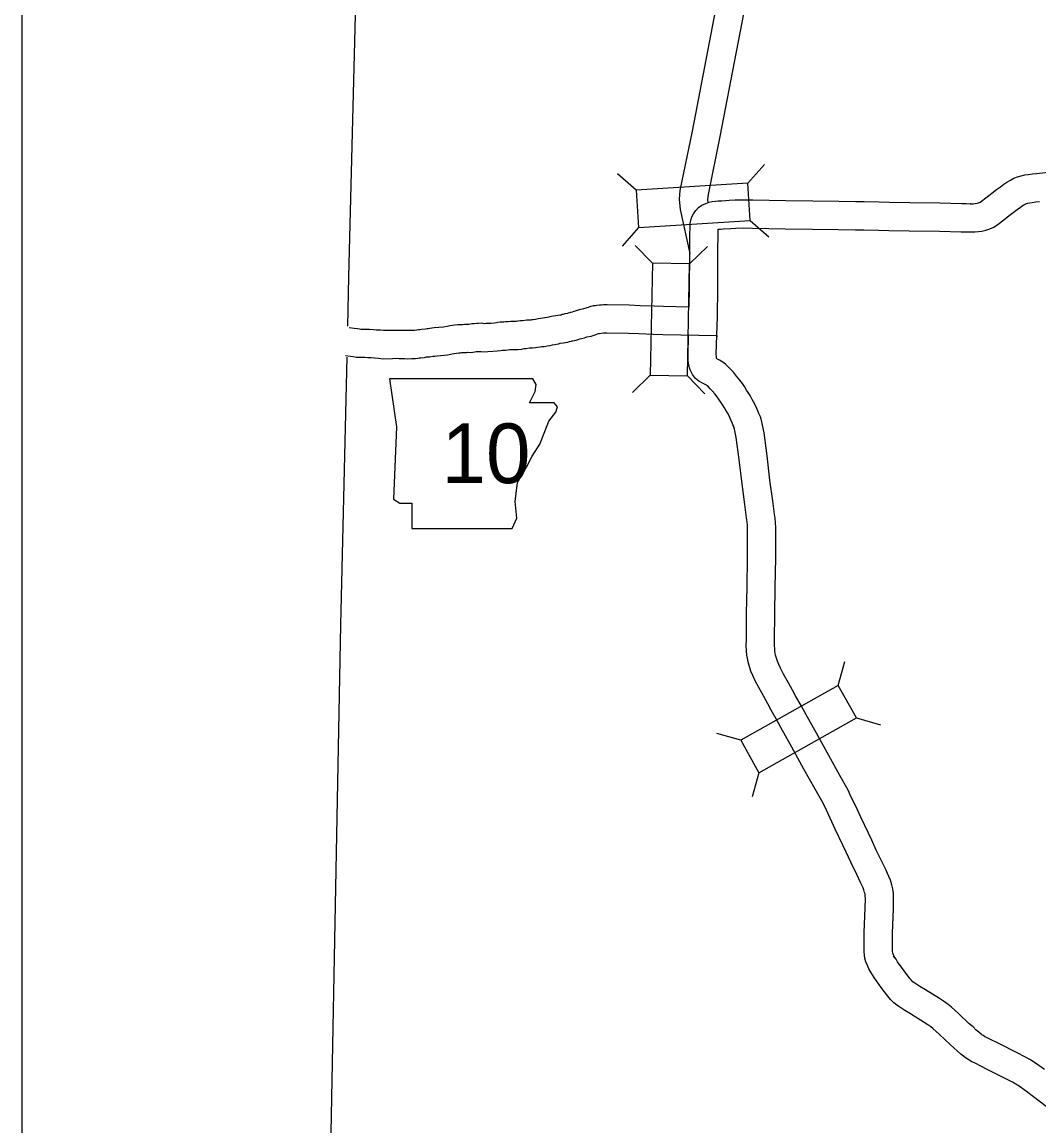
# Model space of a CAD drawing. Extents: x 1370567 to 1373900, y 377514 to 379648.
# Drawn here: x 1370727.3 to 1370835.2, y 379043.8 to 379160.9 of the extents above; entities that cross this region are included whole.
import ezdxf

# ---------------------------------------------------------------- set-up
doc = ezdxf.new("R2010")
doc.units = 0
doc.layers.add('Default', color=7, linetype='Continuous')
doc.layers.add('Survey Symbols', color=7, linetype='Continuous')

msp = doc.modelspace()

# ---------------------------------------------------------------- linework, layer by layer
at = {"layer": 'Default'}
for p, q in [((1370804.33, 379143.81), (1370806.08, 379145.79)), ((1370792.48, 379143.06), (1370790.5, 379144.81)), ((1370827.99, 379141.63), (1370827.95, 379141.63)), ((1370792.72, 379139.11), (1370790.98, 379137.13)), ((1370804.58, 379139.86), (1370806.56, 379138.11)), ((1370827.95, 379138.63), (1370827.99, 379138.63)), ((1370794.19, 379135.31), (1370792.36, 379137.21)), ((1370798.15, 379135.24), (1370800.05, 379137.07)), ((1370788.48, 379127.85), (1370788.56, 379127.87)), ((1370793.97, 379123.43), (1370792.07, 379121.6)), ((1370797.93, 379123.36), (1370799.77, 379121.46)), ((1370813.93, 379090.5), (1370814.64, 379093.04)), ((1370815.87, 379087.05), (1370818.41, 379086.33)), ((1370803.57, 379084.68), (1370801.03, 379085.39)), ((1370805.51, 379081.23), (1370804.8, 379078.68)), ((1370815.8, 379077.68), (1370815.28, 379078.73)), ((1370813.08, 379076.4), (1370812.67, 379077.25)), ((1370819.93, 379061.58), (1370819.79, 379061.82)), ((1370817.22, 379060.29), (1370817.37, 379060.04))]:
    msp.add_line(p, q, dxfattribs=at)
for points in [[(1370761.86, 379128.63), (1370761.98, 379133.85), (1370762.81, 379167.24), (1370763.57, 379194.87), (1370764.84, 379244.73)], [(1370802.56, 379171.53), (1370802.51, 379171.1), (1370802.02, 379168.37), (1370801.85, 379167.28), (1370798.42, 379149.33), (1370797.12, 379143.03), (1370797.05, 379142.1), (1370797.13, 379141), (1370798.16, 379136.33)], [(1370805.54, 379171.16), (1370805.47, 379170.65), (1370804.98, 379167.88), (1370804.81, 379166.77), (1370801.36, 379148.75), (1370800.1, 379142.6), (1370800.06, 379142.09), (1370800.09, 379141.73)], [(1370827.95, 379141.63), (1370828.25, 379141.63), (1370828.47, 379141.65), (1370828.68, 379141.68), (1370828.82, 379141.71), (1370828.9, 379141.74), (1370828.99, 379141.78), (1370829.15, 379141.89), (1370829.6, 379142.24), (1370830.22, 379142.75), (1370830.72, 379143.12), (1370831.14, 379143.43), (1370831.52, 379143.71), (1370831.83, 379143.93), (1370832.2, 379144.14), (1370832.58, 379144.33), (1370832.96, 379144.49), (1370833.35, 379144.6), (1370833.73, 379144.68), (1370834.1, 379144.74), (1370834.56, 379144.79), (1370834.99, 379144.84), (1370836.84, 379145.03)], [(1370798.11, 379130.7), (1370798.14, 379132.71), (1370798.16, 379136.34), (1370798.16, 379136.77), (1370798.17, 379138.26), (1370798.19, 379139.24), (1370798.21, 379139.54), (1370798.3, 379140.01), (1370798.43, 379140.32), (1370798.56, 379140.57), (1370798.8, 379140.92), (1370799.1, 379141.22), (1370799.46, 379141.47), (1370799.86, 379141.66), (1370800.23, 379141.78), (1370800.55, 379141.86), (1370800.89, 379141.9), (1370801.19, 379141.93), (1370801.58, 379141.95), (1370802.35, 379142), (1370802.95, 379142.03), (1370803.83, 379142.05), (1370804.85, 379142.04), (1370808.35, 379141.97), (1370811.24, 379141.94), (1370813.98, 379141.89), (1370815.8, 379141.85), (1370816.67, 379141.85), (1370818.28, 379141.81), (1370819.36, 379141.8), (1370821.52, 379141.75), (1370824.72, 379141.71), (1370827.04, 379141.65), (1370827.52, 379141.64), (1370827.99, 379141.63)], [(1370827.99, 379138.63), (1370828.41, 379138.64), (1370828.81, 379138.67), (1370829.18, 379138.73), (1370829.59, 379138.81), (1370830.02, 379138.95), (1370830.45, 379139.15), (1370830.9, 379139.44), (1370831.49, 379139.91), (1370832.06, 379140.38), (1370832.49, 379140.7), (1370832.92, 379141.01), (1370833.27, 379141.27), (1370833.45, 379141.4), (1370833.63, 379141.5), (1370833.83, 379141.6), (1370833.95, 379141.65), (1370834.07, 379141.68), (1370834.28, 379141.73), (1370834.52, 379141.77), (1370834.9, 379141.81), (1370835.3, 379141.85)], [(1370801.04, 379127.65), (1370801.09, 379129.67), (1370801.14, 379132.68), (1370801.16, 379136.33), (1370801.16, 379136.77), (1370801.17, 379138.22), (1370801.18, 379138.91), (1370801.23, 379138.92), (1370801.43, 379138.94), (1370801.75, 379138.96), (1370802.51, 379139), (1370803.06, 379139.03), (1370803.86, 379139.05), (1370804.82, 379139.04), (1370808.3, 379138.97), (1370811.2, 379138.94), (1370813.93, 379138.89), (1370815.77, 379138.85), (1370816.63, 379138.85), (1370818.23, 379138.81), (1370819.31, 379138.8), (1370821.46, 379138.75), (1370824.66, 379138.71), (1370826.96, 379138.65), (1370827.47, 379138.64), (1370827.95, 379138.63)], [(1370787.75, 379130.76), (1370787.94, 379130.81), (1370788.15, 379130.84), (1370788.3, 379130.87), (1370788.57, 379130.9), (1370788.71, 379130.89), (1370788.78, 379130.9), (1370788.99, 379130.93), (1370789.15, 379130.93), (1370789.2, 379130.93), (1370789.23, 379130.94), (1370789.28, 379130.94), (1370789.38, 379130.94), (1370791.74, 379130.88), (1370792.88, 379130.83), (1370794.37, 379130.78), (1370795.38, 379130.75), (1370798.11, 379130.7)], [(1370762, 379128.5), (1370762.55, 379128.42), (1370762.88, 379128.37), (1370763.1, 379128.34), (1370763.24, 379128.33), (1370763.74, 379128.33), (1370764.17, 379128.3), (1370764.57, 379128.28), (1370764.86, 379128.25), (1370765.34, 379128.24), (1370765.66, 379128.2), (1370765.77, 379128.19), (1370766.53, 379128.2), (1370767.05, 379128.22), (1370767.38, 379128.2), (1370767.65, 379128.21), (1370768.04, 379128.2), (1370768.2, 379128.19), (1370768.55, 379128.22), (1370768.76, 379128.21), (1370768.84, 379128.21), (1370768.94, 379128.22), (1370769.18, 379128.25), (1370769.37, 379128.26), (1370769.49, 379128.27), (1370769.69, 379128.33), (1370770.1, 379128.36), (1370770.26, 379128.37), (1370770.38, 379128.39), (1370770.58, 379128.43), (1370770.79, 379128.45), (1370771.03, 379128.48), (1370772.02, 379128.57), (1370772.41, 379128.64), (1370772.7, 379128.69), (1370772.96, 379128.72), (1370773.22, 379128.77), (1370773.55, 379128.8), (1370773.84, 379128.82), (1370774.04, 379128.82), (1370774.26, 379128.84), (1370774.59, 379128.86), (1370774.71, 379128.85), (1370775.01, 379128.91), (1370775.29, 379128.92), (1370775.55, 379128.94), (1370775.68, 379128.94), (1370776.01, 379128.99), (1370776.38, 379128.93), (1370776.53, 379128.95), (1370777.04, 379128.96), (1370777.38, 379129), (1370777.65, 379129.03), (1370777.79, 379129.06), (1370778.04, 379129.1), (1370778.32, 379129.1), (1370778.43, 379129.1), (1370778.61, 379129.12), (1370778.9, 379129.14), (1370779.17, 379129.15), (1370779.48, 379129.16), (1370779.78, 379129.17), (1370779.9, 379129.18), (1370780.2, 379129.23), (1370780.42, 379129.25), (1370780.88, 379129.32), (1370781.31, 379129.32), (1370781.42, 379129.34), (1370781.53, 379129.35), (1370781.79, 379129.39), (1370782.05, 379129.44), (1370782.33, 379129.47), (1370782.58, 379129.5), (1370782.79, 379129.54), (1370783.06, 379129.59), (1370783.25, 379129.62), (1370783.34, 379129.64), (1370783.5, 379129.68), (1370783.7, 379129.73), (1370783.96, 379129.78), (1370784.36, 379129.83), (1370784.46, 379129.84), (1370784.51, 379129.85), (1370784.62, 379129.89), (1370784.77, 379129.92), (1370784.94, 379129.98), (1370785.19, 379130.02), (1370785.21, 379130.02), (1370785.3, 379130.05), (1370785.52, 379130.11), (1370785.72, 379130.17), (1370785.88, 379130.21), (1370786.03, 379130.25), (1370786.14, 379130.29), (1370786.46, 379130.4), (1370786.93, 379130.49), (1370787.16, 379130.57), (1370787.28, 379130.61), (1370787.4, 379130.65), (1370787.65, 379130.74), (1370787.85, 379130.78)], [(1370761.6, 379125.53), (1370762.13, 379125.45), (1370762.41, 379125.41), (1370762.76, 379125.35), (1370763.16, 379125.33), (1370763.65, 379125.33), (1370763.97, 379125.31), (1370764.35, 379125.29), (1370764.69, 379125.26), (1370765.1, 379125.24), (1370765.35, 379125.21), (1370765.68, 379125.18), (1370766.62, 379125.21), (1370767.02, 379125.22), (1370767.32, 379125.2), (1370767.64, 379125.21), (1370767.9, 379125.2), (1370768.24, 379125.18), (1370768.61, 379125.21), (1370768.68, 379125.21), (1370769.04, 379125.21), (1370769.29, 379125.24), (1370769.45, 379125.26), (1370769.61, 379125.27), (1370770, 379125.31), (1370770.2, 379125.36), (1370770.32, 379125.37), (1370770.57, 379125.39), (1370770.9, 379125.43), (1370771.01, 379125.46), (1370771.1, 379125.46), (1370771.36, 379125.5), (1370772.43, 379125.59), (1370772.94, 379125.69), (1370773.15, 379125.72), (1370773.41, 379125.76), (1370773.63, 379125.8), (1370773.78, 379125.81), (1370773.94, 379125.82), (1370774.2, 379125.82), (1370774.48, 379125.85), (1370774.61, 379125.86), (1370774.91, 379125.85), (1370775.36, 379125.92), (1370775.47, 379125.93), (1370775.65, 379125.94), (1370775.95, 379125.94), (1370776.01, 379125.95), (1370776.29, 379125.9), (1370776.74, 379125.95), (1370777.25, 379125.97), (1370777.71, 379126.02), (1370778.06, 379126.06), (1370778.29, 379126.1), (1370778.3, 379126.1), (1370778.36, 379126.1), (1370778.61, 379126.1), (1370778.85, 379126.13), (1370779.06, 379126.14), (1370779.31, 379126.15), (1370779.57, 379126.16), (1370779.93, 379126.17), (1370780.32, 379126.2), (1370780.57, 379126.25), (1370780.75, 379126.26), (1370781.13, 379126.32), (1370781.48, 379126.33), (1370781.8, 379126.36), (1370781.98, 379126.39), (1370782.29, 379126.43), (1370782.47, 379126.47), (1370782.69, 379126.49), (1370783.04, 379126.54), (1370783.34, 379126.59), (1370783.59, 379126.64), (1370783.82, 379126.68), (1370784.01, 379126.72), (1370784.21, 379126.76), (1370784.34, 379126.8), (1370784.42, 379126.81), (1370784.76, 379126.85), (1370784.96, 379126.88), (1370785.23, 379126.94), (1370785.4, 379126.99), (1370785.61, 379127.04), (1370785.67, 379127.06), (1370785.7, 379127.06), (1370785.9, 379127.1), (1370786.11, 379127.16), (1370786.33, 379127.22), (1370786.5, 379127.27), (1370786.66, 379127.31), (1370786.97, 379127.4), (1370787.18, 379127.48), (1370787.22, 379127.49), (1370787.7, 379127.58), (1370788.11, 379127.72), (1370788.19, 379127.75), (1370788.38, 379127.81), (1370788.48, 379127.85)], [(1370788.56, 379127.87), (1370789, 379127.91), (1370789.14, 379127.92), (1370789.23, 379127.93), (1370789.24, 379127.94), (1370789.27, 379127.94), (1370789.32, 379127.94), (1370789.36, 379127.94), (1370791.65, 379127.88), (1370792.77, 379127.84), (1370794.27, 379127.78), (1370795.32, 379127.75), (1370801.04, 379127.65)], [(1370812.67, 379077.25), (1370812.31, 379077.99), (1370811.48, 379079.49), (1370810.29, 379081.62), (1370808.99, 379083.96), (1370807.84, 379086.02), (1370807.35, 379086.94), (1370806.82, 379087.86), (1370806.44, 379088.55), (1370806.01, 379089.32), (1370805.49, 379090.29), (1370805.11, 379091), (1370804.85, 379091.54), (1370804.66, 379092.03), (1370804.46, 379092.62), (1370804.36, 379093), (1370804.28, 379093.38), (1370804.22, 379093.73), (1370804.18, 379094.17), (1370804.16, 379094.74), (1370804.17, 379095.34), (1370804.19, 379098.18), (1370804.24, 379100.92), (1370804.29, 379104.06), (1370804.3, 379107.19), (1370804.29, 379107.51), (1370804.25, 379107.88), (1370804.2, 379108.28), (1370804, 379109.69), (1370803.71, 379111.9), (1370803.39, 379114.49), (1370803.08, 379116.83), (1370802.95, 379117.52), (1370802.9, 379117.75), (1370802.85, 379117.92), (1370802.83, 379118), (1370802.75, 379118.17), (1370802.65, 379118.42), (1370802.53, 379118.67), (1370802.38, 379119.03), (1370802.17, 379119.42), (1370802, 379119.73), (1370801.84, 379119.97), (1370801.67, 379120.23), (1370801.46, 379120.56), (1370801.28, 379120.82), (1370801.07, 379121.12), (1370800.82, 379121.44), (1370800.54, 379121.77), (1370800.34, 379121.99), (1370800.14, 379122.19), (1370800.02, 379122.31), (1370799.93, 379122.38), (1370799.86, 379122.42), (1370799.74, 379122.48), (1370799.5, 379122.59), (1370799.14, 379122.79), (1370798.76, 379123.09), (1370798.46, 379123.51), (1370798.24, 379123.92), (1370798.14, 379124.22), (1370798.05, 379124.53), (1370798, 379124.94), (1370797.99, 379125.28), (1370797.98, 379125.69), (1370798.04, 379127.58), (1370798.04, 379127.68)], [(1370815.28, 379078.73), (1370814.97, 379079.37), (1370814.1, 379080.95), (1370812.91, 379083.08), (1370811.61, 379085.42), (1370810.47, 379087.46), (1370809.98, 379088.38), (1370809.44, 379089.34), (1370809.06, 379090.01), (1370808.64, 379090.76), (1370808.13, 379091.71), (1370807.79, 379092.34), (1370807.61, 379092.72), (1370807.48, 379093.06), (1370807.33, 379093.5), (1370807.28, 379093.7), (1370807.23, 379093.94), (1370807.2, 379094.13), (1370807.18, 379094.36), (1370807.16, 379094.78), (1370807.17, 379095.31), (1370807.19, 379098.14), (1370807.24, 379100.87), (1370807.29, 379104.03), (1370807.31, 379107.25), (1370807.28, 379107.76), (1370807.22, 379108.25), (1370807.17, 379108.67), (1370806.97, 379110.09), (1370806.68, 379112.28), (1370806.37, 379114.87), (1370806.05, 379117.31), (1370805.89, 379118.13), (1370805.81, 379118.49), (1370805.73, 379118.75), (1370805.66, 379119.01), (1370805.51, 379119.36), (1370805.39, 379119.63), (1370805.27, 379119.9), (1370805.08, 379120.34), (1370804.8, 379120.86), (1370804.57, 379121.27), (1370804.36, 379121.6), (1370804.2, 379121.85), (1370803.96, 379122.22), (1370803.75, 379122.53), (1370803.48, 379122.9), (1370803.14, 379123.34), (1370802.79, 379123.74), (1370802.54, 379124.03), (1370802.22, 379124.36), (1370801.97, 379124.59), (1370801.67, 379124.82), (1370801.32, 379125.04), (1370801.05, 379125.18), (1370800.99, 379125.21), (1370800.99, 379125.33), (1370800.98, 379125.68), (1370801.04, 379127.65), (1370801.04, 379127.49)], [(1370759.6, 379016.99), (1370761.13, 379096.92), (1370761.78, 379125.33)], [(1370835.82, 379049.75), (1370834.97, 379050.34), (1370834.69, 379050.53), (1370834.45, 379050.68), (1370834.25, 379050.8), (1370833.82, 379051.03), (1370832.85, 379051.53), (1370831.11, 379052.42), (1370829.82, 379053.08), (1370829.46, 379053.25), (1370829.31, 379053.34), (1370829.18, 379053.42), (1370829.12, 379053.47), (1370828.85, 379053.69), (1370828.58, 379053.92), (1370828.24, 379054.25), (1370827.84, 379054.6), (1370826.68, 379055.68), (1370825.95, 379056.35), (1370825.59, 379056.65), (1370825.1, 379056.98), (1370824.66, 379057.27), (1370823.18, 379058.18), (1370822.6, 379058.54), (1370822.06, 379058.89), (1370821.89, 379059.02), (1370821.84, 379059.06), (1370821.66, 379059.24), (1370821.51, 379059.41), (1370820.91, 379060.21), (1370820.23, 379061.17), (1370820.06, 379061.44), (1370819.93, 379061.64), (1370819.85, 379061.78), (1370819.79, 379061.91), (1370819.72, 379062.08), (1370819.71, 379062.12), (1370819.7, 379062.25), (1370819.68, 379062.43), (1370819.67, 379062.74), (1370819.69, 379064.22), (1370819.78, 379066.8), (1370819.81, 379067.87), (1370819.78, 379068.42), (1370819.73, 379068.91), (1370819.62, 379069.33), (1370819.48, 379069.84), (1370819.31, 379070.23), (1370819.17, 379070.55), (1370819, 379070.91), (1370818.59, 379071.73), (1370817.97, 379073.03), (1370817.48, 379074.07), (1370817.13, 379074.82), (1370816.33, 379076.53), (1370815.8, 379077.68)], [(1370832.79, 379048.18), (1370832.42, 379048.38), (1370831.49, 379048.85), (1370829.74, 379049.75), (1370828.47, 379050.4), (1370828.05, 379050.6), (1370827.78, 379050.76), (1370827.45, 379050.96), (1370827.22, 379051.15), (1370826.93, 379051.38), (1370826.57, 379051.69), (1370826.2, 379052.04), (1370825.83, 379052.37), (1370824.65, 379053.48), (1370823.98, 379054.08), (1370823.77, 379054.25), (1370823.43, 379054.49), (1370823.05, 379054.74), (1370821.61, 379055.63), (1370821, 379056), (1370820.35, 379056.42), (1370820.01, 379056.67), (1370819.8, 379056.86), (1370819.47, 379057.18), (1370819.18, 379057.51), (1370818.48, 379058.44), (1370817.74, 379059.5), (1370817.55, 379059.8), (1370817.37, 379060.07), (1370817.16, 379060.43), (1370817.02, 379060.76), (1370816.86, 379061.17), (1370816.76, 379061.57), (1370816.72, 379061.88), (1370816.68, 379062.21), (1370816.67, 379062.72), (1370816.69, 379064.29), (1370816.78, 379066.91), (1370816.81, 379067.84), (1370816.79, 379068.18), (1370816.77, 379068.38), (1370816.73, 379068.54), (1370816.65, 379068.82), (1370816.56, 379069.03), (1370816.44, 379069.3), (1370816.3, 379069.6), (1370815.89, 379070.42), (1370815.26, 379071.75), (1370814.77, 379072.79), (1370814.41, 379073.54), (1370813.61, 379075.26), (1370813.08, 379076.4)], [(1370836.01, 379045.81), (1370834.53, 379046.96), (1370834.07, 379047.31), (1370833.26, 379047.87), (1370833.03, 379048.03), (1370832.9, 379048.11), (1370832.79, 379048.18)]]:
    msp.add_lwpolyline(points, dxfattribs=at)
for points in [[(1370804.33, 379143.81), (1370792.48, 379143.06), (1370792.72, 379139.11), (1370804.58, 379139.86)], [(1370794.19, 379135.31), (1370793.97, 379123.43), (1370797.93, 379123.36), (1370798.15, 379135.24)], [(1370766.27, 379123.04), (1370767.04, 379117.96), (1370766.7, 379110.27), (1370767.37, 379109.84), (1370768.64, 379109.84), (1370768.64, 379107.14), (1370779.3, 379107.14), (1370779.81, 379108.24), (1370779.64, 379110.01), (1370779.89, 379112.04), (1370780.82, 379113.65), (1370781.42, 379114.84), (1370782.26, 379116.1), (1370782.77, 379117.46), (1370783.19, 379118.56), (1370783.95, 379119.49), (1370784.12, 379120.08), (1370783.78, 379120.5), (1370781.16, 379120.5), (1370781.75, 379121.69), (1370781.84, 379122.45), (1370781.49, 379123.03)], [(1370805.51, 379081.23), (1370815.87, 379087.05), (1370813.93, 379090.5), (1370803.57, 379084.68)]]:
    msp.add_lwpolyline(points, close=True, dxfattribs=at)
at = {"layer": 'Survey Symbols'}
msp.add_lwpolyline([(1370727.27, 379552.54), (1371456.67, 379552.54), (1371456.67, 378768.06), (1370727.27, 378768.06)], close=True, dxfattribs=at)
msp.add_lwpolyline([(1370727.27, 379552.54), (1371456.67, 379552.54), (1371456.67, 378768.06), (1370727.27, 378768.06)], close=True, dxfattribs=at)
msp.add_lwpolyline([(1370727.27, 379552.54), (1371456.67, 379552.54), (1371456.67, 378768.06), (1370727.27, 378768.06)], close=True, dxfattribs=at)
msp.add_lwpolyline([(1370727.27, 379552.54), (1371456.67, 379552.54), (1371456.67, 378768.06), (1370727.27, 378768.06)], close=True, dxfattribs=at)
msp.add_lwpolyline([(1370727.27, 379552.54), (1371456.67, 379552.54), (1371456.67, 378768.06), (1370727.27, 378768.06)], close=True, dxfattribs=at)
msp.add_lwpolyline([(1370727.27, 379552.54), (1371456.67, 379552.54), (1371456.67, 378768.06), (1370727.27, 378768.06)], close=True, dxfattribs=at)

# ---------------------------------------------------------------- texts
at = {"layer": 'Default'}
msp.add_text('10', height=6.336, dxfattribs=at).set_placement((1370771.82, 379111.97))

doc.saveas('drawing.dxf')
